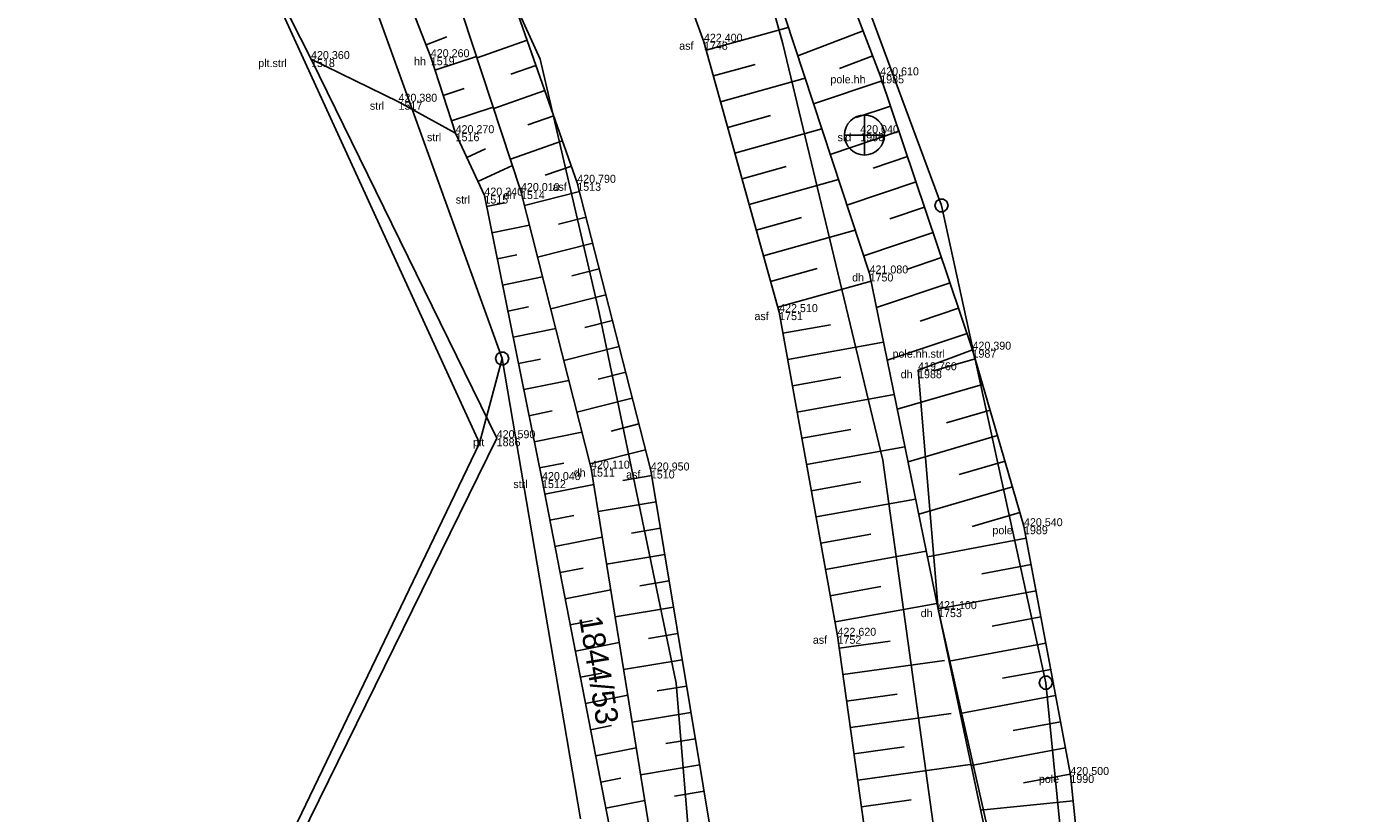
# Model space of a CAD drawing. Extents: x -747792 to -745414, y -1093712 to -1091463.
# Drawn here: x -746682.53 to -746632.74, y -1092574.51 to -1092545 of the extents above; entities that cross this region are included whole.
import ezdxf

# ---------------------------------------------------------------- set-up
doc = ezdxf.new("R2010")
doc.units = 0
for name, color, linetype in [('Doplňující texty', 7, 'Continuous'), ('Hladina', 7, 'Continuous'), ('Koleje_dopravní prvky', 7, 'Continuous'), ('Nezařazené objekty', 7, 'Continuous'), ('Nivelační značky_hrany', 7, 'Continuous'), ('Pracovní_bod JDTM STC_VC - výška', 7, 'Continuous'), ('Pracovní_bod PPBP', 7, 'Continuous'), ('Rozhraní ploch', 7, 'Continuous'), ('Stromy_porost', 7, 'Continuous'), ('Výškopis', 7, 'Continuous'), ('Čísla popisná_parcelní', 7, 'Continuous')]:
    doc.layers.add(name, color=color, linetype=linetype)

msp = doc.modelspace()

# ---------------------------------------------------------------- linework, layer by layer
at = {"layer": 'Doplňující texty'}
for points in [[(-746648.145, -1092551.47), (-746648.02, -1092551.565), (-746647.97, -1092551.71), (-746648.02, -1092551.855), (-746648.145, -1092551.95), (-746648.295, -1092551.95), (-746648.42, -1092551.855), (-746648.47, -1092551.71), (-746648.42, -1092551.565), (-746648.295, -1092551.47)], [(-746664.625, -1092557.21), (-746664.5, -1092557.305), (-746664.45, -1092557.45), (-746664.5, -1092557.595), (-746664.625, -1092557.69), (-746664.775, -1092557.69), (-746664.9, -1092557.595), (-746664.95, -1092557.45), (-746664.9, -1092557.305), (-746664.775, -1092557.21)], [(-746644.235, -1092569.37), (-746644.11, -1092569.465), (-746644.06, -1092569.61), (-746644.11, -1092569.755), (-746644.235, -1092569.85), (-746644.385, -1092569.85), (-746644.51, -1092569.755), (-746644.56, -1092569.61), (-746644.51, -1092569.465), (-746644.385, -1092569.37)]]:
    msp.add_lwpolyline(points, close=True, dxfattribs=at)
for points in [[(-746648.245, -1092551.71), (-746648.195, -1092551.71)], [(-746664.725, -1092557.45), (-746664.675, -1092557.45)], [(-746644.335, -1092569.61), (-746644.285, -1092569.61)]]:
    msp.add_lwpolyline(points, dxfattribs=at)
at = {"layer": 'Hladina'}
for p, q in [((-746657.13, -1092545.57), (-746657.13, -1092545.57)), ((-746671.86, -1092546.22), (-746671.86, -1092546.22)), ((-746667.37, -1092546.15), (-746667.37, -1092546.15)), ((-746650.52, -1092546.83), (-746650.52, -1092546.83)), ((-746668.58, -1092547.82), (-746668.58, -1092547.82)), ((-746666.44, -1092549), (-746666.44, -1092549)), ((-746651.27, -1092549), (-746651.27, -1092549)), ((-746661.88, -1092550.86), (-746661.88, -1092550.86)), ((-746665.36, -1092551.34), (-746665.36, -1092551.34)), ((-746663.99, -1092551.17), (-746663.99, -1092551.17)), ((-746650.92, -1092554.26), (-746650.92, -1092554.26)), ((-746654.31, -1092555.71), (-746654.31, -1092555.71)), ((-746647.06, -1092557.12), (-746647.06, -1092557.12)), ((-746649.1, -1092557.89), (-746649.1, -1092557.89)), ((-746664.9, -1092560.44), (-746664.9, -1092560.44)), ((-746663.2, -1092562.01), (-746663.2, -1092562.01)), ((-746661.36, -1092561.58), (-746661.36, -1092561.58)), ((-746659.12, -1092561.65), (-746659.12, -1092561.65)), ((-746645.13, -1092563.74), (-746645.13, -1092563.74)), ((-746648.35, -1092566.85), (-746648.35, -1092566.85)), ((-746652.12, -1092567.85), (-746652.12, -1092567.85)), ((-746643.39, -1092573.07), (-746643.39, -1092573.07))]:
    msp.add_line(p, q, dxfattribs=at)
at = {"layer": 'Nezařazené objekty'}
msp.add_lwpolyline([(-746674.37, -1092579.73), (-746664.9, -1092560.44), (-746671.86, -1092546.22), (-746685.68, -1092519.02)], dxfattribs=at)
at = {"layer": 'Nivelační značky_hrany'}
for points in [[(-746676.15, -1092504.12), (-746670.74, -1092515.64), (-746665.13, -1092526.07), (-746661.01, -1092534.91), (-746657.13, -1092545.57), (-746654.31, -1092555.71), (-746652.12, -1092567.85), (-746649.95, -1092583.4), (-746648.25, -1092600.5), (-746646.08, -1092622.58)], [(-746640.293, -1092727.76), (-746642.73, -1092706.84), (-746645.07, -1092684.23), (-746647.45, -1092662.17), (-746649.23, -1092645.87), (-746651.64, -1092623.4), (-746654, -1092600.5), (-746655.65, -1092585.38), (-746656.67, -1092576.42), (-746659.12, -1092561.65), (-746661.88, -1092550.86), (-746667.11, -1092535.97), (-746671.93, -1092526), (-746677.329, -1092516.06)]]:
    msp.add_lwpolyline(points, dxfattribs=at)
at = {"layer": 'Pracovní_bod JDTM STC_VC - výška'}
for points in [[(-746632.74, -1092626.58), (-746635.64, -1092620.77), (-746637.67, -1092615.33), (-746638.38, -1092607.28), (-746642.34, -1092583.46), (-746643.39, -1092573.07), (-746645.13, -1092563.74), (-746647.06, -1092557.12), (-746650.52, -1092546.83), (-746656.13, -1092532.17), (-746659.53, -1092519.12), (-746666.48, -1092509.53), (-746671.18, -1092501.38)], [(-746671.86, -1092546.22), (-746668.58, -1092547.82), (-746666.44, -1092549)], [(-746666.44, -1092549), (-746665.36, -1092551.34), (-746663.2, -1092562.01), (-746660.43, -1092576.24), (-746658.93, -1092586.95), (-746657.16, -1092600.72), (-746656.07, -1092616.52), (-746651.4, -1092662.02)], [(-746647.06, -1092557.12), (-746649.1, -1092557.89), (-746648.35, -1092566.85), (-746644.58, -1092583.56), (-746643.94, -1092588.6), (-746643.94, -1092602.65), (-746640.7, -1092621.81)]]:
    msp.add_lwpolyline(points, dxfattribs=at)
at = {"layer": 'Pracovní_bod PPBP'}
for points in [[(-746674.28, -1092503.22), (-746668.93, -1092514.2), (-746662.98, -1092525.23), (-746658.61, -1092533.49), (-746654.09, -1092544.66), (-746650.92, -1092554.26), (-746648.35, -1092566.85), (-746644.79, -1092583.69), (-746644.13, -1092588.78), (-746644.17, -1092602.45), (-746642.4, -1092621.5)], [(-746643.03, -1092728.31), (-746645.35, -1092706.55), (-746647.64, -1092685.53), (-746650.22, -1092662.21), (-746652.01, -1092645.97), (-746654.41, -1092623.21), (-746657.16, -1092600.72), (-746657.52, -1092586.28), (-746659.03, -1092575.98), (-746661.36, -1092561.58), (-746663.99, -1092551.17), (-746668.72, -1092536.82), (-746673.6, -1092526.76), (-746679.03, -1092516.89)], [(-746680.19, -1092517.45), (-746674.6, -1092527.64), (-746667.37, -1092546.15), (-746666.44, -1092549)], [(-746657.041, -1092545.891), (-746653.966, -1092545.036)], [(-746667.55, -1092545.689), (-746666.773, -1092545.386)], [(-746663.758, -1092545.515), (-746665.637, -1092546.175)], [(-746651.158, -1092545.162), (-746653.614, -1092546.101)], [(-746667.213, -1092546.631), (-746665.654, -1092546.122)], [(-746650.801, -1092546.096), (-746652.051, -1092546.574)], [(-746663.426, -1092546.458), (-746664.375, -1092546.791)], [(-746656.773, -1092546.854), (-746655.212, -1092546.42)], [(-746656.505, -1092547.818), (-746653.338, -1092546.937)], [(-746650.452, -1092547.033), (-746653.021, -1092547.896)], [(-746666.903, -1092547.581), (-746666.122, -1092547.326)], [(-746663.095, -1092547.402), (-746665.01, -1092548.074)], [(-746666.593, -1092548.532), (-746665.028, -1092548.021)], [(-746650.133, -1092547.98), (-746651.42, -1092548.413)], [(-746662.763, -1092548.345), (-746663.73, -1092548.685)], [(-746656.237, -1092548.781), (-746654.631, -1092548.334)], [(-746655.969, -1092549.744), (-746652.71, -1092548.838)], [(-746649.814, -1092548.928), (-746652.394, -1092549.796)], [(-746666.021, -1092549.908), (-746665.32, -1092549.584)], [(-746662.432, -1092549.289), (-746664.384, -1092549.974)], [(-746649.496, -1092549.876), (-746650.788, -1092550.311)], [(-746665.602, -1092550.816), (-746664.304, -1092550.217)], [(-746662.101, -1092550.232), (-746663.086, -1092550.578)], [(-746655.701, -1092550.708), (-746654.049, -1092550.248)], [(-746655.433, -1092551.671), (-746652.083, -1092550.739)], [(-746649.177, -1092550.824), (-746651.767, -1092551.695)], [(-746661.797, -1092551.184), (-746663.854, -1092551.71)], [(-746665.276, -1092551.754), (-746664.594, -1092551.616)], [(-746648.858, -1092551.772), (-746650.156, -1092552.208)], [(-746665.078, -1092552.735), (-746663.667, -1092552.449)], [(-746661.549, -1092552.153), (-746662.579, -1092552.416)], [(-746655.165, -1092552.635), (-746653.467, -1092552.162)], [(-746654.897, -1092553.598), (-746651.455, -1092552.641)], [(-746648.54, -1092552.72), (-746651.14, -1092553.594)], [(-746664.879, -1092553.715), (-746664.15, -1092553.567)], [(-746661.301, -1092553.122), (-746663.364, -1092553.649)], [(-746654.629, -1092554.562), (-746652.885, -1092554.076)], [(-746648.221, -1092553.667), (-746649.54, -1092554.111)], [(-746664.681, -1092554.695), (-746663.176, -1092554.39)], [(-746661.054, -1092554.09), (-746662.086, -1092554.355)], [(-746654.361, -1092555.525), (-746650.861, -1092554.551)], [(-746660.806, -1092555.059), (-746662.874, -1092555.588)], [(-746647.902, -1092554.615), (-746650.658, -1092555.542)], [(-746664.482, -1092555.675), (-746663.707, -1092555.518)], [(-746647.583, -1092555.563), (-746649.02, -1092556.046)], [(-746660.558, -1092556.028), (-746661.593, -1092556.293)], [(-746664.284, -1092556.655), (-746662.686, -1092556.331)], [(-746654.167, -1092556.505), (-746652.38, -1092556.183)], [(-746647.265, -1092556.511), (-746650.255, -1092557.517)], [(-746660.31, -1092556.997), (-746662.384, -1092557.527)], [(-746653.989, -1092557.489), (-746650.393, -1092556.841)], [(-746664.086, -1092557.635), (-746663.263, -1092557.469)], [(-746646.96, -1092557.463), (-746648.52, -1092557.918)], [(-746660.062, -1092557.966), (-746661.101, -1092558.231)], [(-746663.887, -1092558.615), (-746662.196, -1092558.273)], [(-746653.812, -1092558.473), (-746652.002, -1092558.147)], [(-746646.68, -1092558.423), (-746649.88, -1092559.356)], [(-746659.815, -1092558.935), (-746661.894, -1092559.466)], [(-746653.634, -1092559.457), (-746649.993, -1092558.801)], [(-746663.689, -1092559.595), (-746662.82, -1092559.419)], [(-746646.4, -1092559.383), (-746648.04, -1092559.861)], [(-746659.567, -1092559.903), (-746660.608, -1092560.17)], [(-746663.49, -1092560.575), (-746661.705, -1092560.214)], [(-746653.456, -1092560.442), (-746651.625, -1092560.111)], [(-746646.12, -1092560.343), (-746649.478, -1092561.322)], [(-746659.319, -1092560.872), (-746661.404, -1092561.406)], [(-746653.279, -1092561.426), (-746649.593, -1092560.761)], [(-746663.292, -1092561.556), (-746662.376, -1092561.37)], [(-746645.84, -1092561.303), (-746647.559, -1092561.804)], [(-746659.088, -1092561.844), (-746660.173, -1092562.025)], [(-746663.098, -1092562.536), (-746661.263, -1092562.179)], [(-746653.101, -1092562.41), (-746651.247, -1092562.075)], [(-746645.56, -1092562.263), (-746649.077, -1092563.289)], [(-746658.924, -1092562.831), (-746661.099, -1092563.192)], [(-746652.924, -1092563.394), (-746649.193, -1092562.721)], [(-746662.906, -1092563.518), (-746662.005, -1092563.343)], [(-746645.281, -1092563.223), (-746647.078, -1092563.748)], [(-746658.76, -1092563.817), (-746659.85, -1092563.998)], [(-746652.746, -1092564.378), (-746650.87, -1092564.04)], [(-746662.715, -1092564.5), (-746660.943, -1092564.155)], [(-746645.045, -1092564.194), (-746648.751, -1092564.885)], [(-746658.597, -1092564.804), (-746660.78, -1092565.166)], [(-746652.569, -1092565.362), (-746648.793, -1092564.681)], [(-746662.524, -1092565.481), (-746661.654, -1092565.312)], [(-746644.862, -1092565.177), (-746646.707, -1092565.521)], [(-746658.433, -1092565.791), (-746659.527, -1092565.972)], [(-746652.391, -1092566.346), (-746650.492, -1092566.004)], [(-746662.333, -1092566.463), (-746660.624, -1092566.13)], [(-746644.679, -1092566.16), (-746648.351, -1092566.845)], [(-746658.27, -1092566.777), (-746660.46, -1092567.14)], [(-746652.214, -1092567.33), (-746648.393, -1092566.641)], [(-746662.142, -1092567.444), (-746661.303, -1092567.281)], [(-746644.495, -1092567.143), (-746646.32, -1092567.483)], [(-746658.106, -1092567.764), (-746659.203, -1092567.946)], [(-746661.951, -1092568.426), (-746660.304, -1092568.105)], [(-746652.055, -1092568.317), (-746650.144, -1092568.051)], [(-746644.312, -1092568.126), (-746647.937, -1092568.802)], [(-746657.942, -1092568.75), (-746660.141, -1092569.115)], [(-746651.917, -1092569.308), (-746648.109, -1092568.776)], [(-746661.76, -1092569.408), (-746660.952, -1092569.25)], [(-746644.129, -1092569.109), (-746645.93, -1092569.445)], [(-746657.779, -1092569.737), (-746658.88, -1092569.919)], [(-746661.569, -1092570.389), (-746659.985, -1092570.081)], [(-746651.778, -1092570.298), (-746649.881, -1092570.034)], [(-746643.945, -1092570.092), (-746647.523, -1092570.76)], [(-746657.615, -1092570.723), (-746659.821, -1092571.089)], [(-746651.64, -1092571.289), (-746647.86, -1092570.761)], [(-746661.378, -1092571.371), (-746660.601, -1092571.219)], [(-746643.762, -1092571.075), (-746645.539, -1092571.407)], [(-746657.451, -1092571.71), (-746658.556, -1092571.893)], [(-746661.187, -1092572.352), (-746659.665, -1092572.056)], [(-746651.502, -1092572.279), (-746649.619, -1092572.016)], [(-746643.579, -1092572.058), (-746647.11, -1092572.717)], [(-746657.288, -1092572.696), (-746659.502, -1092573.063)], [(-746651.364, -1092573.27), (-746647.144, -1092572.681)], [(-746660.996, -1092573.334), (-746660.25, -1092573.189)], [(-746643.395, -1092573.042), (-746645.149, -1092573.369)], [(-746657.124, -1092573.683), (-746658.233, -1092573.867)], [(-746651.225, -1092574.26), (-746649.356, -1092573.999)], [(-746660.805, -1092574.315), (-746659.345, -1092574.031)], [(-746643.292, -1092574.036), (-746646.757, -1092574.386)]]:
    msp.add_lwpolyline(points, dxfattribs=at)
at = {"layer": 'Stromy_porost'}
for points in [[(-746665.55, -1092560.62), (-746684.57, -1092519.09)], [(-746675.9, -1092526.38), (-746664.7, -1092557.45)], [(-746654.17, -1092545.65), (-746657.06, -1092535.18)], [(-746663.27, -1092546.22), (-746668.02, -1092535.77)], [(-746648.22, -1092551.71), (-746653.31, -1092537.97)], [(-746650.42, -1092561.26), (-746654.17, -1092545.65)], [(-746661.06, -1092555.73), (-746663.27, -1092546.22)], [(-746644.31, -1092569.61), (-746648.22, -1092551.71)], [(-746658.17, -1092569.63), (-746661.06, -1092555.73)], [(-746665.55, -1092560.62), (-746664.7, -1092557.45)], [(-746664.7, -1092557.45), (-746661.76, -1092574.72)], [(-746674.69, -1092579.67), (-746665.55, -1092560.62)], [(-746648.04, -1092578.51), (-746650.42, -1092561.26)], [(-746656.79, -1092586.25), (-746658.17, -1092569.63)], [(-746644.31, -1092569.61), (-746641.76, -1092595.34)]]:
    msp.add_lwpolyline(points, dxfattribs=at)
at = {"layer": 'Čísla popisná_parcelní'}
for p, q in [((-746651.111, -1092549.818), (-746651.11, -1092548.323)), ((-746650.358, -1092549.076), (-746651.858, -1092549.071))]:
    msp.add_line(p, q, dxfattribs=at)
msp.add_circle((-746651.11, -1092549.07), 0.75, dxfattribs=at)

# ---------------------------------------------------------------- texts
at = {"layer": 'Koleje_dopravní prvky'}
msp.add_text('1844/53', height=0.85, rotation=279.2596, dxfattribs=at).set_placement((-746661.812, -1092567.168))
at = {"layer": 'Rozhraní ploch'}
for s, p in [(' asf', (-746658.167, -1092545.87)), ('1748', (-746657.13, -1092545.87)), (' plt.strl', (-746673.95, -1092546.52)), ('1518', (-746671.86, -1092546.52)), (' hh', (-746668.109, -1092546.45)), ('1519', (-746667.37, -1092546.45)), (' pole.hh', (-746652.499, -1092547.13)), ('1985', (-746650.52, -1092547.13)), (' strl', (-746669.766, -1092548.12)), ('1517', (-746668.58, -1092548.12)), (' strl', (-746667.626, -1092549.3)), ('1516', (-746666.44, -1092549.3)), (' sld', (-746652.231, -1092549.3)), ('1986', (-746651.27, -1092549.3)), (' asf', (-746662.917, -1092551.16)), ('1513', (-746661.88, -1092551.16)), (' strl', (-746666.546, -1092551.64)), ('1515', (-746665.36, -1092551.64)), (' dh', (-746664.755, -1092551.47)), ('1514', (-746663.99, -1092551.47)), (' dh', (-746651.685, -1092554.56)), ('1750', (-746650.92, -1092554.56)), (' asf', (-746655.347, -1092556.01)), ('1751', (-746654.31, -1092556.01)), (' pole.hh.strl', (-746650.17, -1092557.42)), ('1987', (-746647.06, -1092557.42)), (' dh', (-746649.865, -1092558.19)), ('1988', (-746649.1, -1092558.19)), (' plt', (-746665.899, -1092560.74)), ('1886', (-746664.9, -1092560.74)), (' strl', (-746664.386, -1092562.31)), ('1512', (-746663.2, -1092562.31)), (' dh', (-746662.125, -1092561.88)), ('1511', (-746661.36, -1092561.88)), (' asf', (-746660.157, -1092561.95)), ('1510', (-746659.12, -1092561.95)), (' pole', (-746646.424, -1092564.04)), ('1989', (-746645.13, -1092564.04)), (' dh', (-746649.115, -1092567.15)), ('1753', (-746648.35, -1092567.15)), (' asf', (-746653.157, -1092568.15)), ('1752', (-746652.12, -1092568.15)), (' pole', (-746644.684, -1092573.37)), ('1990', (-746643.39, -1092573.37))]:
    msp.add_text(s, height=0.3, dxfattribs=at).set_placement(p)
at = {"layer": 'Výškopis'}
for s, p in [('422,400', (-746657.13, -1092545.57)), ('420,360', (-746671.86, -1092546.22)), ('420,260', (-746667.37, -1092546.15)), ('420,610', (-746650.52, -1092546.83)), ('420,380', (-746668.58, -1092547.82)), ('420,270', (-746666.44, -1092549)), ('420,040', (-746651.27, -1092549)), ('420,790', (-746661.88, -1092550.86)), ('420,240', (-746665.36, -1092551.34)), ('420,010', (-746663.99, -1092551.17)), ('421,080', (-746650.92, -1092554.26)), ('422,510', (-746654.31, -1092555.71)), ('420,390', (-746647.06, -1092557.12)), ('419,760', (-746649.1, -1092557.89)), ('420,590', (-746664.9, -1092560.44)), ('420,110', (-746661.36, -1092561.58)), ('420,950', (-746659.12, -1092561.65)), ('420,040', (-746663.2, -1092562.01)), ('420,540', (-746645.13, -1092563.74)), ('421,100', (-746648.35, -1092566.85)), ('422,620', (-746652.12, -1092567.85)), ('420,500', (-746643.39, -1092573.07))]:
    msp.add_text(s, height=0.3, dxfattribs=at).set_placement(p)

doc.saveas('drawing.dxf')
